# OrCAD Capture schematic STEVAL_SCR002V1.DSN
size A4
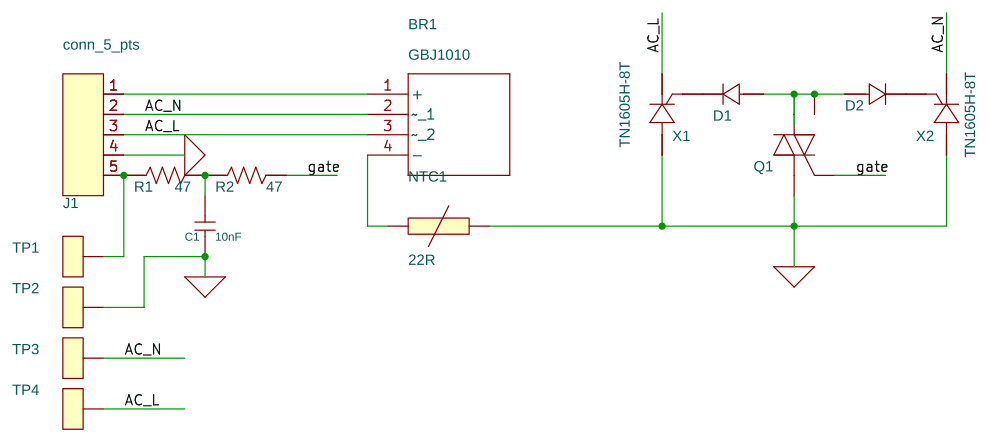
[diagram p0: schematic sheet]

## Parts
BR1  GBJ1010  [GBJ1006]
C1  10nF  [cms1206]
D1  STTH110  [sma]
D2  STTH110  [sma]
J1  conn_5_pts  [con_5pts_RS_pas3_5mm]
NTC1  22R  [NTC_S238_EPCOS]
Q1  Z0110MN  [SOT230P700X180-4N]
R1  47  [cms1206]
R2  47  [cms1206]
TP1  test point  [test_point]
TP2  test point  [test_point]
TP3  test point  [test_point]
TP4  test point  [test_point]
X1  TN1605H-8T  [TO220AB]
X2  TN1605H-8T  [TO220AB]

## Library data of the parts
BR1 = GBJ1006: Manufacturer_Part_Number: BR1010SG; RS Part Number: 917-8792; distry: RS; ref_distri: 823-4068; value_BOM: GBJ bridge rectifier, 10 A , 1000 V
C1 = capa_Y2_470pf: Type: X7R; ref distri: 2534062; value_BOM: 10nF_25V_10%_X7R_SMD_0805
D1 D2 = STTH110: value_BOM: STMICROELECTRONICS_STTH110A
J1 = conn_5_pts: distri: RS; ref distri: 8971348; value_BOM: 5 Way PCB Terminal Block_3.5mmm pitch
NTC1 = R_0: distri: RS; ref distri: 216-1400; value_BOM: NTC_22R
Q1 = Z0110MN_2: value_BOM: STMICROELECTRONICS_Z0110MN
R1 R2 = R: distri: RS; ref distri: 693-4491; value_BOM: 47R_5%_0.75W_1206
TP1-TP4 = test_point_small: value_BOM: manuf:VERO_REF:20-2136
X1 X2 = TN1205H-6G_0: value_BOM: STMICROELECTRONICS_TN1605H-6T

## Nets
GND_SIGNAL: C1.2 J1.4 NTC1.1 Q1.1(A1) TP2.1(A) X1.2(A) X2.2(A)
AC_L: BR1.3(~_2) J1.3 TP4.1(A) X1.1(K)
AC_N: BR1.2(~_1) J1.2 TP3.1(A) X2.1(K)
gate: Q1.3(G) R2.2
N7629489: D1.2(A) D2.2(A) Q1.2(A2_1) Q1.4(A2_2)
N7631947: BR1.4(-) NTC1.2
N7637748: BR1.1(+) J1.1
N7638738: C1.1 R1.2 R2.1
N7639486: J1.5 R1.1 TP1.1(A)
N7641422: D1.1(K) X1.3(G)
N7641445: D2.1(K) X2.3(G)
